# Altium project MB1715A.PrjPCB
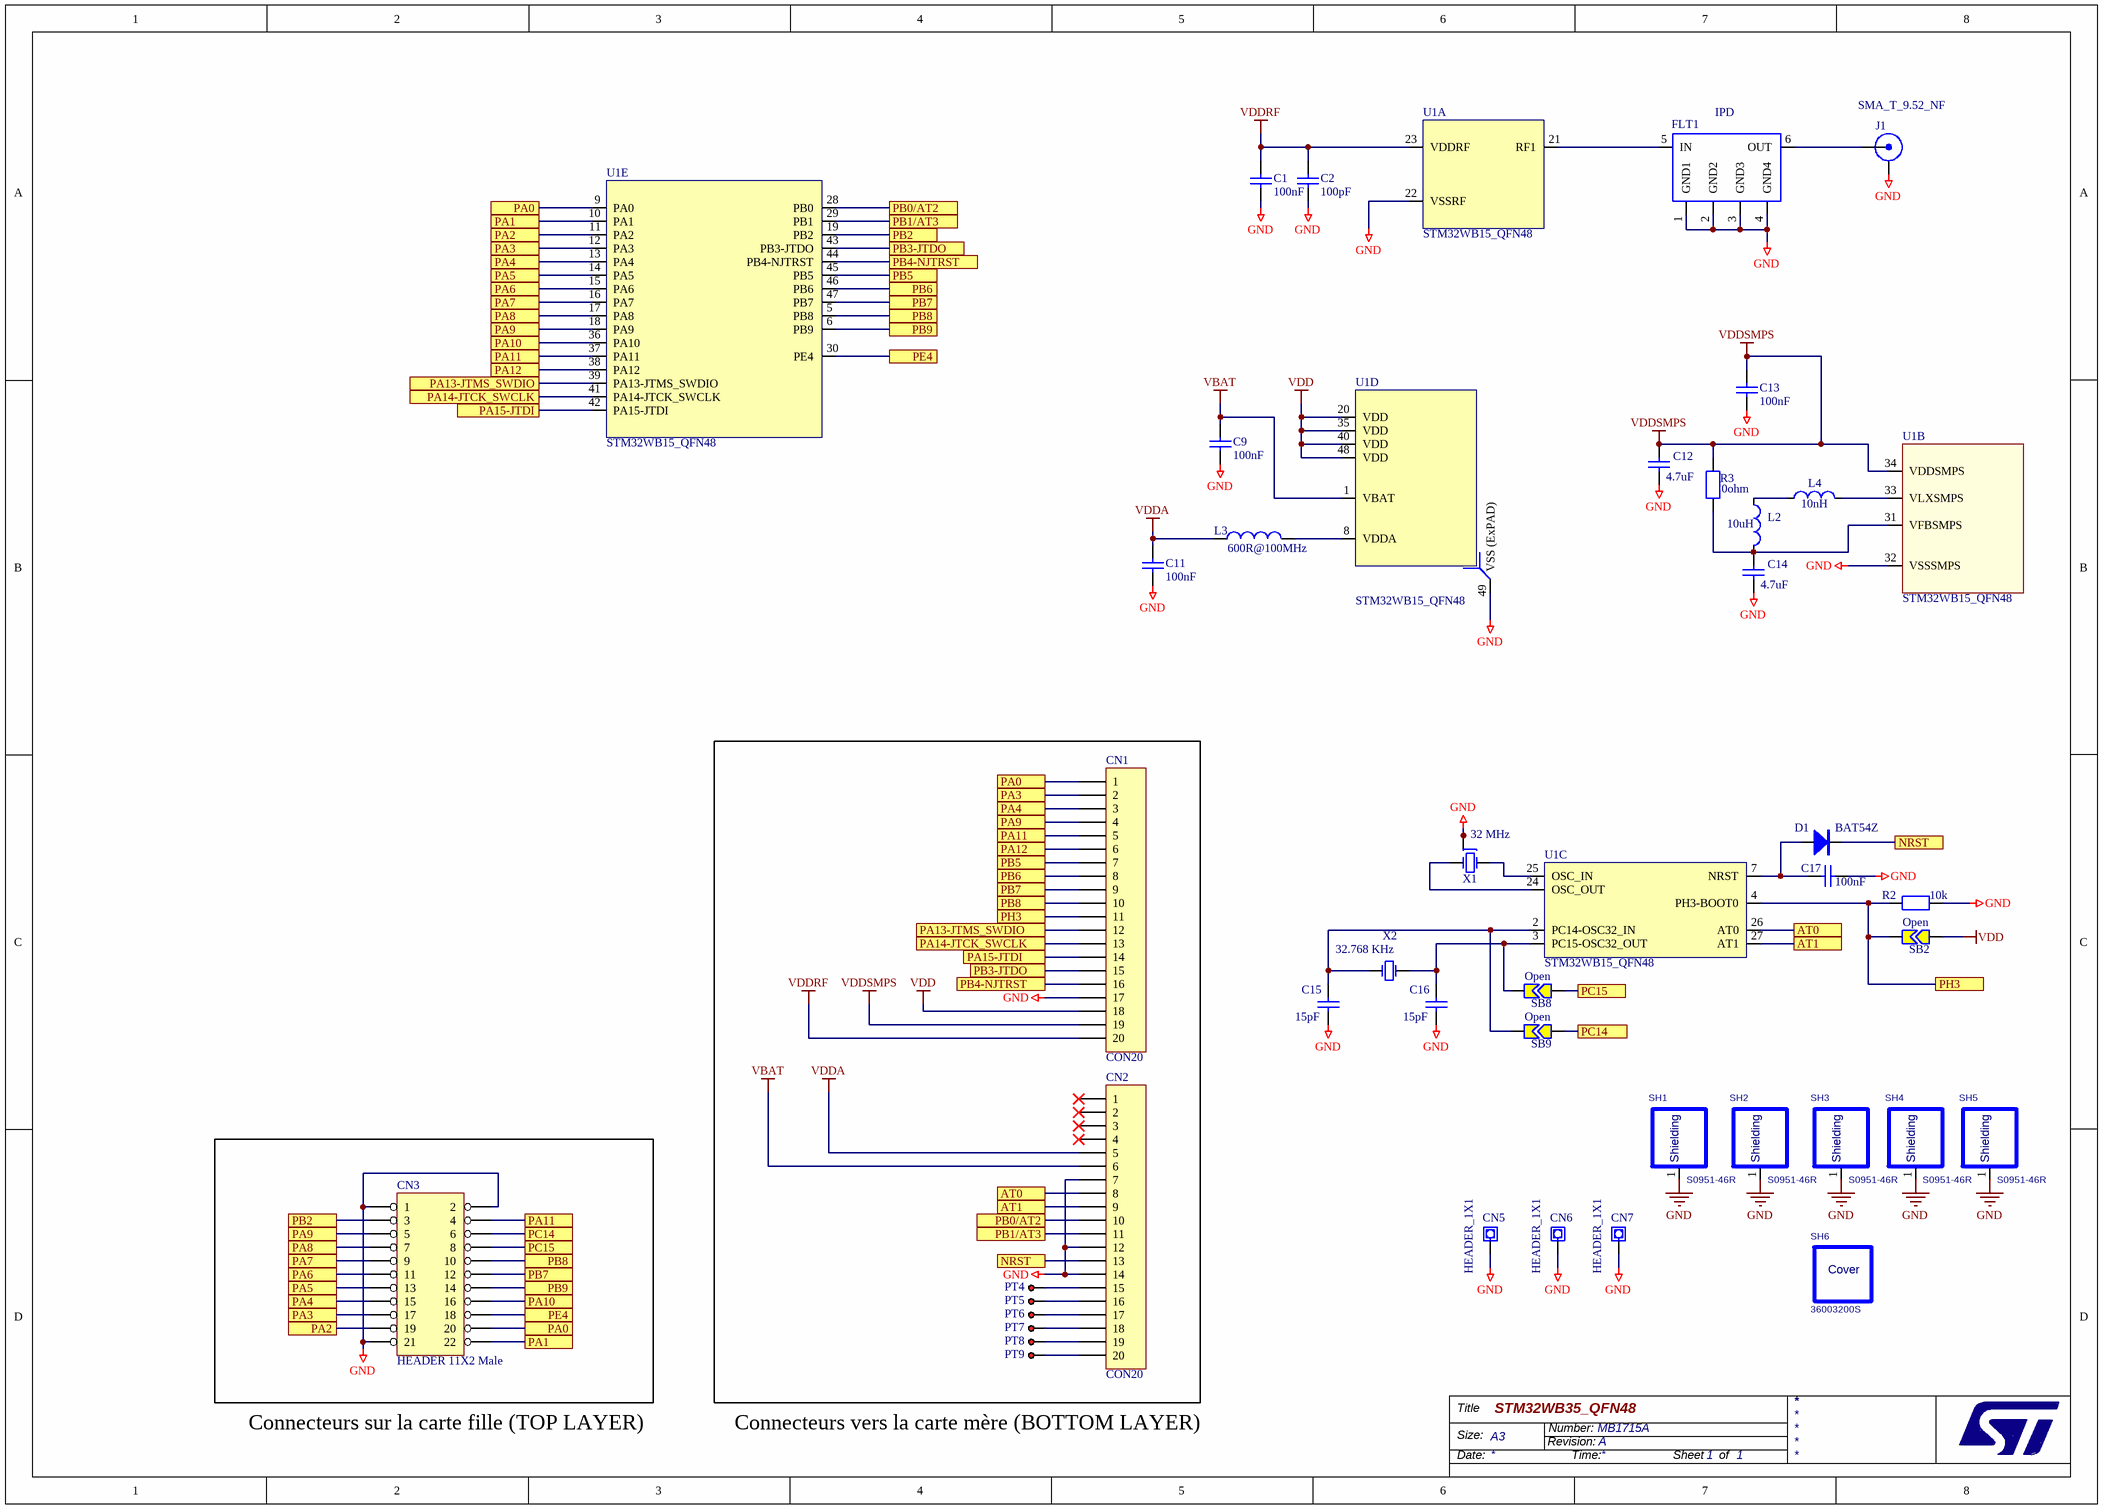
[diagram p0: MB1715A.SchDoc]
Business _Number: AF2007-016; Checked_By: M. LAURY; Delivery_Date: 21/08/2020; Format: A4; PCB_Designer: M. JULLIG; Ref_Customer: MB1715A; Title_Board: STM32WB35 QFN48
1 sheet, 42 parts. Net scope: flat (ports and power ports of the same name join across sheets).
Board file: MB1715A.PcbDoc

## Sheet MB1715A.SchDoc: STM32WB35_QFN48
size A3; DocumentNumber: MB1715A; Revision: A; SheetNumber: 1; SheetTotal: 1

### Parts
C1  value 100nF  [CAPC1005X06N]
C2  value 100pF  [CAPC1005X06N]
C9  value 100nF  [CAPC1005X06N]
C11  value 100nF  [CAPC1005X06N]
C12  value 4.7uF  [CAPC1005X06N]
C13  value 100nF  [CAPC1005X06N]
C14  value 4.7uF  [CAPC1005X06N]
C15  value 15pF  [CAPC1005X06N]
C16  value 15pF  [CAPC1005X06N]
C17  value 100nF  [CAPC1005X06N]
CN1  CON20  [CO_SAMTEC_TSW-120-07-x-S]
CN2  CON20  [CO_SAMTEC_TSW-120-07-x-S]
CN3  HEADER 11X2 Male  [CO_SAMTEC_TSW-111-07-x-D]
CN5  HEADER_1X1  [TP_KEYSTONE_5001]
CN6  HEADER_1X1  [TP_KEYSTONE_5001]
CN7  HEADER_1X1  [TP_KEYSTONE_5001]
D1  BAT54Z  [SOD123_KA]
FLT1  IPD  [IPD]
J1  SMA_T_9.52_NF  [SAMTEC_SMA-J-P-H-ST-EM1]
L2  value 10uH  [IND_MURATA_0805]  (hidden comment: 10uH - LQM21FN100M70L)
L3  value 600R@100MHz  [INDC1608X95N]
L4  value 10nH  [IND_MURATA_0402]  (hidden comment: 10nH - LQG15WZ10NJ02D)
PT4  PT  [TP140x70H]  (value not drawn)
PT5  PT  [TP140x70H]  (value not drawn)
PT6  PT  [TP140x70H]  (value not drawn)
PT7  PT  [TP140x70H]  (value not drawn)
PT8  PT  [TP140x70H]  (value not drawn)
PT9  PT  [TP140x70H]  (value not drawn)
R2  value 10k  [RESC1005X04N]  (hidden comment: Resistor)
R3  value 0ohm  [RESC1005X04N]  (hidden comment: Resistor)
SB2  Open  [GC_0402]
SB8  Open  [GC_0402]
SB9  Open  [GC_0402]
SH1  S0951-46R  [SHIELD_HARWIN_S0951-46R]
SH2  S0951-46R  [SHIELD_HARWIN_S0951-46R]
SH3  S0951-46R  [SHIELD_HARWIN_S0951-46R]
SH4  S0951-46R  [SHIELD_HARWIN_S0951-46R]
SH5  S0951-46R  [SHIELD_HARWIN_S0951-46R]
SH6  36003200S  [SHIELD_WURTH_36003200S]
U1  STM32WB15_QFN48  [STM32WBxx_QFN48]  (parts A,B,C,D,E of 5)
X1  value 32 MHz  [OSC_NDK_NX2016SA]  (hidden comment: NX2016_32M)
X2  value 32.768 KHz  [OSC_NDK_NX2012SA]  (hidden comment: NX2012_32K768)

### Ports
AT0, AT1, NRST, PA0, PA1, PA2, PA3, PA4, PA5, PA6, PA7, PA8, PA9, PA10, PA11, PA12, PA13-JTMS_SWDIO, PA14-JTCK_SWCLK, PA15-JTDI, PB0/AT2, PB1/AT3, PB2, PB3-JTDO, PB4-NJTRST, PB5, PB6, PB7, PB8, PB9, PC14, PC15, PE4, PH3

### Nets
GND: C1.1 C2.1 C9.1 C11.1 C12.2 C13.1 C14.2 C15.2 C16.2 C17.1 CN1.17 CN2.7 CN2.12 CN2.14 CN3.1 CN3.2 CN3.21 CN5.1 CN6.1 CN7.1 FLT1.1(GND1) FLT1.2(GND2) FLT1.3(GND3) FLT1.4(GND4) J1.2(Y) R2.2 SH1.1 SH2.1 SH3.1 SH4.1 SH5.1 U1.22(VSSRF) U1.32(VSSSMPS) U1.49(VSS_(ExPAD)) X1.2 X1.4
VBAT: C9.2 CN2.6 U1.1(VBAT)
VDD: CN1.18 SB2.1 U1.20(VDD) U1.35(VDD) U1.40(VDD) U1.48(VDD)
VDDA: C11.2 CN2.5 L3.1
VDDRF: C1.2 C2.2 CN1.20 U1.23(VDDRF)
VDDSMPS: C12.1 C13.2 CN1.19 R3.1 U1.34(VDDSMPS)
AT0: CN2.8 U1.26(AT0) ; port AT0
AT1: CN2.9 U1.27(AT1) ; port AT1
NRST: CN2.13 D1.K ; port NRST
PA0: CN1.1 CN3.20 U1.9(PA0) ; port PA0
PA1: CN3.22 U1.10(PA1) ; port PA1
PA2: CN3.19 U1.11(PA2) ; port PA2
PA3: CN1.2 CN3.17 U1.12(PA3) ; port PA3
PA4: CN1.3 CN3.15 U1.13(PA4) ; port PA4
PA5: CN3.13 U1.14(PA5) ; port PA5
PA6: CN3.11 U1.15(PA6) ; port PA6
PA7: CN3.9 U1.16(PA7) ; port PA7
PA8: CN3.7 U1.17(PA8) ; port PA8
PA9: CN1.4 CN3.5 U1.18(PA9) ; port PA9
PA10: CN3.16 U1.36(PA10) ; port PA10
PA11: CN1.5 CN3.4 U1.37(PA11) ; port PA11
PA12: CN1.6 U1.38(PA12) ; port PA12
PA13-JTMS_SWDIO: CN1.12 U1.39(PA13-JTMS_SWDIO) ; port PA13-JTMS_SWDIO
PA14-JTCK_SWCLK: CN1.13 U1.41(PA14-JTCK_SWCLK) ; port PA14-JTCK_SWCLK
PA15-JTDI: CN1.14 U1.42(PA15-JTDI) ; port PA15-JTDI
PB0/AT2: CN2.10 U1.28(PB0) ; port PB0/AT2
PB1/AT3: CN2.11 U1.29(PB1) ; port PB1/AT3
PB2: CN3.3 U1.19(PB2) ; port PB2
PB3-JTDO: CN1.15 U1.43(PB3-JTDO) ; port PB3-JTDO
PB4-NJTRST: CN1.16 U1.44(PB4-NJTRST) ; port PB4-NJTRST
PB5: CN1.7 U1.45(PB5) ; port PB5
PB6: CN1.8 U1.46(PB6) ; port PB6
PB7: CN1.9 CN3.12 U1.47(PB7) ; port PB7
PB8: CN1.10 CN3.10 U1.5(PB8) ; port PB8
PB9: CN3.14 U1.6(PB9) ; port PB9
PC14: CN3.6 SB9.1 ; port PC14
PC15: CN3.8 SB8.1 ; port PC15
PE4: CN3.18 U1.30(PE4) ; port PE4
PH3: CN1.11 R2.1 SB2.2 U1.4(PH3-BOOT0) ; port PH3
NetC14_1: C14.1 L2.2 R3.2 U1.31(VFBSMPS)
NetC15_1: C15.1 SB9.2 U1.2(PC14-OSC32_IN) X2.1(OSC1)
NetC16_1: C16.1 SB8.2 U1.3(PC15-OSC32_OUT) X2.2(OSC2)
NetC17_2: C17.2 D1.A U1.7(NRST)
NetCN2_15: CN2.15 PT4.1
NetCN2_16: CN2.16 PT5.1
NetCN2_17: CN2.17 PT6.1
NetCN2_18: CN2.18 PT7.1
NetCN2_19: CN2.19 PT8.1
NetCN2_20: CN2.20 PT9.1
NetFLT1_5: FLT1.5(IN) U1.21(RF1)
NetFLT1_6: FLT1.6(OUT) J1.1(X)
NetL2_1: L2.1 L4.1
NetL3_2: L3.2 U1.8(VDDA)
NetL4_2: L4.2 U1.33(VLXSMPS)
NetU1_24: U1.24(OSC_OUT) X1.3(OSC2)
NetU1_25: U1.25(OSC_IN) X1.1(OSC1)

Not connected (* = marked no-connect by the designer): CN2 1* 2* 3* 4*

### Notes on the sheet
- Connecteurs sur la carte fille (TOP LAYER)
- Connecteurs vers la carte mère (BOTTOM LAYER)

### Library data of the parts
C1 C9 C11 C13 C17 = MCD-00102: Capacitor, MLCC, 100nF, 16V, X7R, 10%, 0402, T=0,5mm; Manufacturer_Part_Number: CC0402KRX7R7BB104; Manufacturer: YAGEO
C2 = MCD-00102: Capacitor, MLCC, 100pF, 50V, C0G, 5%, 0402, T=0,5mm; Manufacturer_Part_Number: CC0402JRNPO9BN101; Manufacturer: YAGEO
C12 C14 = MCD-00102: Capacitor, MLCC, 4.7uF, 10V, X5R, 10%, 0402, T=0,5mm; Manufacturer_Part_Number: C1005X5R1A475K050BC; Manufacturer: TDK
C15 C16 = MCD-00102: Capacitor, MLCC, 4.3pF, 50V, C0G, ±0.1pF, 0402, T=0,5mm; Manufacturer_Part_Number: C0402C439B5GACTU; Manufacturer: KEMET
CN1 CN2 = CON20: Connector right-angle, pitch 2.54mm, 20 contacts; Manufacturer: SAMTEC; Manufacturer_Part_Number: TSW-120-07-L-S
CN3 = HEADER 11X2: Connector right-angle, pitch 2.54mm, 2x11 contacts; Manufacturer: SAMTEC; Manufacturer_Part_Number: TSW-111-07-L-D
CN5-CN7 = HEADER_1X1: PC Test point miniature - Black; Manufacturer: KEYSTONE; Manufacturer_Part_Number: 5001
D1 = BAT54K: Schottky Diode; Manufacturer: STMICROELECTRONICS; Manufacturer_Part_Number: BAT54ZFILM
J1 = SMA_T_9.52_NF: SMA Jack, Edge Mount, 50 Ohms; Manufacturer: SAMTEC; Manufacturer_Part_Number: SMA-J-P-H-ST-EM1
L2 = IND_LQM21FN100M70L: Inductor, 10uH, 20%, 100mA, 0805; Manufacturer: Murata
L3 = MCD-00047: SMD Chip ferrite bead, 600R@100MHz +/-25%, 350mA, 500mohm DC, 0603, T=0.8mm; Manufacturer_Part_Number: FCM1608KF-601T03; Manufacturer: TAI-TECH
L4 = IND_LQM21FN100M70L: Inductor, 10nH, 5%, 500mA, 0402; Manufacturer: Murata
PT4-PT9 = PT: Point de test PCB
R2 = RES: Resistor,10K,0402,1%,1/10W; Manufacturer: VISHAY; Manufacturer_Part_Number: MCS04020C1002FE000
R3 = RES: Resistor,0ohm,0402,1/10W
SB2 SB8 SB9 = Strap2: Solder Jumper - Open
SH1-SH5 = EMI_WURTH_36103255: Shield clips S0951-46R; Manufacturer: Harwin; ERP Code: A Codifier; Do Not Mount: DNM; Conformite: ROHS
SH6 = EMI_WURTH_36003250: WE-SHC Shielding Cover 20x20mm - SMD; Manufacturer: Wurth; ERP Code: A Codifier; Do Not Mount: DNM; Conformite: ROHS
X1 = NX2016_32M: Crystal 32 MHz, 8pF, -+10 PPM, R=60Ω, SMD; Manufacturer: NDK; Manufacturer_Part_Number: NX2016SA 32 MHz EXS00A-CS06654
X2 = NX2012_32K768: Crystal NDK 2.0x1.2mm  32.768 KHz; Manufacturer_Part_Number: NX2012SA 32.768KHz  EXS00A-MU00389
